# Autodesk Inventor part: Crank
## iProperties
Author: Administrator
Shininess: 27.0
PropertySet Name: _Private Model Information
Created: 2001-04
Part Number: Crank
Document SubType Name: Modeling
Designer: Administrator
Control State: 0
Master: False
Checked Out: False
PropertySet Name: Design Tracking Control
Density: 0.0
Volumn: 0.0
Area: 0.0
PropertySet Name: Model Information
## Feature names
1. Extrusion1
2. Revolution1
3. Extrusion2
4. Revolution2
